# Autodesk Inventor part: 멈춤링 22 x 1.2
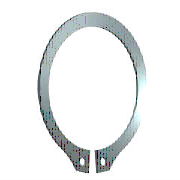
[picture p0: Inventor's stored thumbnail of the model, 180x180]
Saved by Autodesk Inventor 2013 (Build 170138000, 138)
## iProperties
IsCustomPart: 0
Created: 2015-11
Part Number: 멈춤링 22 x 1.2
Material: 스테인리스강
Description: 리테이닝 링(C형)
Document SubType Name: Modeling
Standard: KS B 1336
Designer: mdu
Standards Organization: KS
Language: ko-KR
Size Designation: 22 x 1.2
Categories: <MemberInstance><Categories><Category DisplayName="샤프트 부품" InternalName="7f7aeb1f-a693-4053-b835-cee3144e0d98" Mnemonic="SHFT"><Category DisplayName="써클립" Inter
Density: 8.08 g/cm^3
Mass: 1.87977 g
Surface Area: 5.91219 cm^2
Volume: 0.232645 cm^3
Author: mdu
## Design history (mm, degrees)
sketch "스케치1"
  geometry: L1 (-6, 0)-(6, 0) reference; L2 (0, 20.189)-(0, -80.536) reference; L3 (-48.09, 0)-(48.09, 0) reference; L4 (-0.5, -21.488)-(-0.5, -25.588); L5 (-0.5, -6.54)-(-0.5, -13.29); L6 (-2.795, 2.7)-(3.672, 2.7); L7 (0.5, -6.54)-(0.5, -13.29); L8 (0.5, -21.488)-(0.5, -25.588); C1 r 1 at (-2, -23.437); C2 r 1 at (2, -23.437); A1 r 10.5 centre (0, -11) between (0.5, -21.488) and (-0.5, -21.488); A2 r 13.025 centre (0, -10.325) between (5.149, -22.289) and (-5.149, -22.289); A3 r 14.597 centre (0, -11) between (-2.318, -25.411) and (-0.5, -25.588); A4 r 2 centre (-2, -23.437) between (-3.97, -23.781) and (-2.318, -25.411); A5 r 2 centre (-5.94, -24.126) between (-3.97, -23.781) and (-5.149, -22.289); A6 r 2 centre (5.94, -24.126) between (5.149, -22.289) and (3.97, -23.781); A7 r 2 centre (2, -23.437) between (2.318, -25.411) and (3.97, -23.781); A8 r 14.597 centre (0, -11) between (0.5, -25.588) and (2.318, -25.411)
  constraints: 16 point on circle, 12 end point, 10 centre point, 9 symmetric about line, 5 point on line, 4 tangent, 3 coincident, 2 horizontal, 1 perpendicular, 1 vertical, 5 other
  dimensions: "d0" = 21 diameter of A1 (= ND); "d1" = 4.1 distance of L4.end L4.start (= SRB2); "d6" = 0.5 distance between parallel lines of L2 L5 (= 0.25 x SD5); "d7" = 2.7 distance between parallel lines of L6 L3 (= SRB1); "d8" = 0.675 distance of A1.centre A2.centre (= 0.25 x SRB1); "d9" = 2 radius of A4 (= SD5); "d10" = 2 radius of A5 (= SD5); "d11" = 1.5 distance from line of L4 A4.centre (= 0.75 x SD5); "d12" = 2 diameter of C1 (= SD5); "d13" = 2 diameter of C2 (= SD5); "d14" = 11 distance from line of A1.centre L1 (= 0.5 x WD)
extrude "본체" new body sketch "스케치1" distance "d2" = 1.2 (= SD); taper "d3" = 0 deg
workaxis "Work Axis1"
workplane "Work Plane1"
body "Solid1"
other parameters: "WD" = 22 (= WDMIN) [user parameter; used in 1 equation term], "SD" = 1.2 [user parameter; used in 1 equation term], "SRB1" = 2.7 [user parameter; used in 2 equation terms], "ND" = 21 [user parameter; used in 1 equation term], "SRB2" = 4.1 [user parameter; used in 1 equation term], "SD5" = 2 [user parameter; used in 6 equation terms], "d15" = 0, "d16" = 0, "d17" = 0, "d41" = 0, "d42" = 0, "WDMIN" = 22 [user parameter; used in 1 equation term], "SD3" = 20.5 [user parameter], "WDMAX" = 24 [user parameter]
